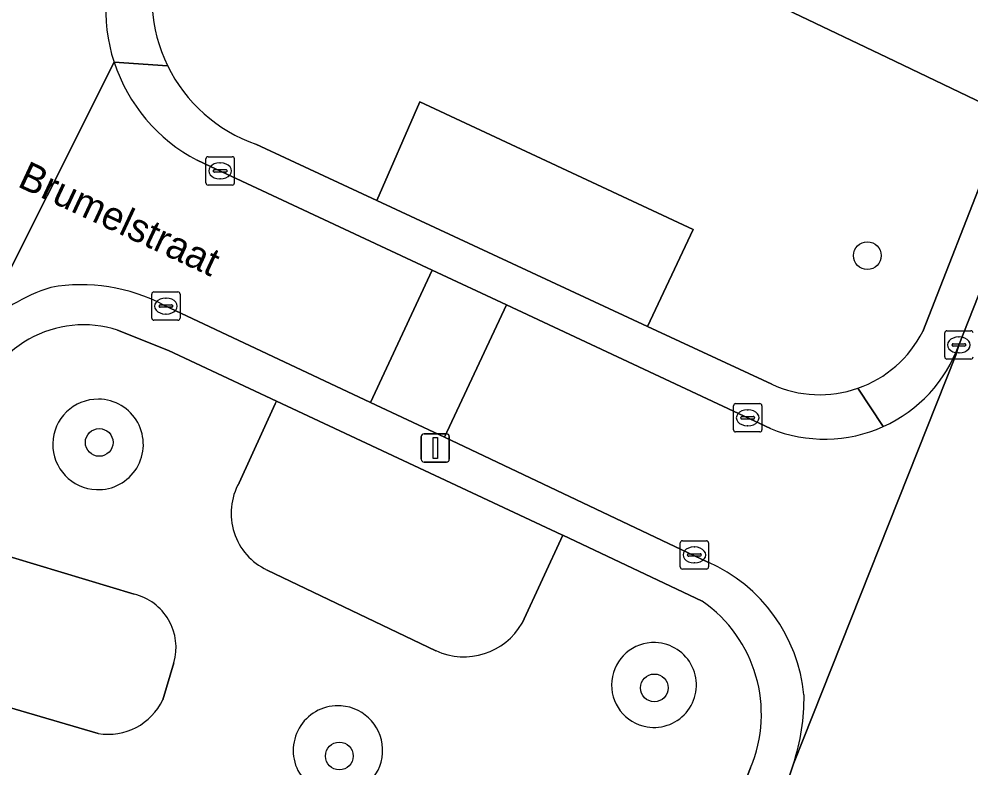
# Model space of a CAD drawing. Extents: x 159817 to 160765, y 380688 to 381638.
# Drawn here: x 160248.03 to 160281.64, y 381228.53 to 381254.99 of the extents above; entities that cross this region are included whole.
import ezdxf

# ---------------------------------------------------------------- set-up
doc = ezdxf.new("R2010")
doc.units = 0
for name, color, linetype in [('IMGEO_Boom', 7, 'Continuous'), ('IMGEO_Groenvoorziening', 7, 'Continuous'), ('IMGEO_Kolk', 7, 'Continuous'), ('IMGEO_Lichtmast', 7, 'Continuous'), ('IMGEO_Openbare_ruimte_label', 7, 'Continuous'), ('IMGEO_Rijbaan_lokaal_open', 7, 'Continuous'), ('IMGEO_Voetpad_open', 7, 'Continuous')]:
    doc.layers.add(name, color=color, linetype=linetype)

msp = doc.modelspace()

# ---------------------------------------------------------------- linework, layer by layer
at = {"layer": 'IMGEO_Boom'}
for centre in [(160277.982, 381246.629), (160250.861, 381240.029), (160270.46, 381231.359), (160259.338, 381228.952)]:
    msp.add_circle(centre, 0.489, dxfattribs=at)
at = {"layer": 'IMGEO_Groenvoorziening'}
for points in [[(160272.065, 381256.79), (160278.685, 381253.622), (160282.93, 381251.591), (160284.608, 381255.87), (160280.242, 381257.583), (160263.914, 381264.002), (160257.027, 381266.942), (160255.623, 381263.651), (160262.284, 381260.57), (160265.98, 381258.86)], [(160267.231, 381236.749), (160267.191, 381236.768), (160257.123, 381241.49), (160257.077, 381241.391), (160255.799, 381238.604)], [(160252.092, 381234.668), (160245.216, 381236.743), (160243.781, 381231.814), (160250.825, 381229.75)], [(160265.791, 381233.649), (160267.231, 381236.749)], [(160256.786, 381235.522), (160262.748, 381232.673)], [(160253.107, 381230.939), (160253.496, 381232.248)]]:
    msp.add_lwpolyline(points, dxfattribs=at)
msp.add_lwpolyline([(160262.176, 381252.064), (160260.664, 381248.573), (160270.213, 381244.128), (160271.829, 381247.547)], close=True, dxfattribs=at)
for centre, radius, start, end in [((160250.82, 381239.959), 1.599, 89.3897, 268.1383), ((160250.82, 381239.959), 1.599, 268.1402, 89.3877), ((160257.732, 381237.524), 2.214, 150.799, 244.716), ((160251.637, 381232.787), 1.936, 343.8475, 76.3941), ((160263.737, 381234.821), 2.364, 245.2691, 330.2968), ((160270.447, 381231.462), 1.498, 87.912, 260.5676), ((160270.447, 381231.462), 1.498, 260.5851, 87.8946), ((160251.179, 381231.856), 2.135, 260.4664, 334.5757), ((160259.29, 381229.15), 1.58, 86.1039, 266.9673), ((160259.288, 381229.15), 1.58, 267.0129, 86.0583)]:
    msp.add_arc(centre, radius, start, end, dxfattribs=at)
at = {"layer": 'IMGEO_Kolk'}
for p, q in [((160254.63, 381249.196), (160254.63, 381250.048)), ((160254.705, 381250.122), (160255.557, 381250.122)), ((160255.631, 381250.048), (160255.631, 381249.196)), ((160254.932, 381249.665), (160255.33, 381249.665)), ((160255.118, 381249.902), (160255.143, 381249.902)), ((160254.889, 381249.616), (160254.889, 381249.628)), ((160255.327, 381249.579), (160254.929, 381249.579)), ((160255.141, 381249.342), (160255.116, 381249.342)), ((160255.373, 381249.628), (160255.373, 381249.616)), ((160255.557, 381249.122), (160254.705, 381249.122)), ((160252.715, 381244.419), (160252.715, 381245.271)), ((160252.79, 381245.345), (160253.642, 381245.345)), ((160253.716, 381245.271), (160253.716, 381244.419)), ((160253.203, 381245.125), (160253.228, 381245.125)), ((160252.974, 381244.839), (160252.974, 381244.851)), ((160253.412, 381244.802), (160253.014, 381244.802)), ((160253.017, 381244.888), (160253.415, 381244.888)), ((160253.458, 381244.851), (160253.458, 381244.839)), ((160253.642, 381244.345), (160252.79, 381244.345)), ((160253.226, 381244.565), (160253.201, 381244.565)), ((160280.786, 381243.974), (160281.638, 381243.974)), ((160280.711, 381243.048), (160280.711, 381243.9)), ((160281.199, 381243.754), (160281.224, 381243.754)), ((160280.97, 381243.468), (160280.97, 381243.48)), ((160281.408, 381243.431), (160281.01, 381243.431)), ((160281.013, 381243.517), (160281.411, 381243.517)), ((160281.454, 381243.48), (160281.454, 381243.468)), ((160281.638, 381242.974), (160280.786, 381242.974)), ((160281.222, 381243.194), (160281.197, 381243.194)), ((160273.254, 381240.473), (160273.254, 381241.325)), ((160273.329, 381241.399), (160274.181, 381241.399)), ((160274.255, 381241.325), (160274.255, 381240.473)), ((160273.513, 381240.893), (160273.513, 381240.905)), ((160273.556, 381240.942), (160273.954, 381240.942)), ((160273.742, 381241.179), (160273.767, 381241.179)), ((160273.997, 381240.905), (160273.997, 381240.893)), ((160273.951, 381240.856), (160273.553, 381240.856)), ((160273.765, 381240.619), (160273.74, 381240.619)), ((160274.181, 381240.399), (160273.329, 381240.399)), ((160271.449, 381236.556), (160272.301, 381236.556)), ((160271.374, 381235.63), (160271.374, 381236.482)), ((160271.862, 381236.336), (160271.887, 381236.336)), ((160272.375, 381236.482), (160272.375, 381235.63)), ((160271.633, 381236.05), (160271.633, 381236.062)), ((160272.071, 381236.013), (160271.673, 381236.013)), ((160271.676, 381236.099), (160272.074, 381236.099)), ((160272.117, 381236.062), (160272.117, 381236.05)), ((160272.301, 381235.556), (160271.449, 381235.556)), ((160271.885, 381235.776), (160271.86, 381235.776))]:
    msp.add_line(p, q, dxfattribs=at)
for points in [[(160254.63, 381249.196), (160254.63, 381250.048)], [(160254.705, 381250.122), (160255.557, 381250.122)], [(160255.631, 381250.048), (160255.631, 381249.196)], [(160255.557, 381249.122), (160254.705, 381249.122)], [(160252.715, 381244.419), (160252.715, 381245.271)], [(160252.79, 381245.345), (160253.642, 381245.345)], [(160253.716, 381245.271), (160253.716, 381244.419)], [(160253.642, 381244.345), (160252.79, 381244.345)], [(160280.786, 381243.974), (160281.638, 381243.974)], [(160280.711, 381243.048), (160280.711, 381243.9)], [(160281.638, 381242.974), (160280.786, 381242.974)], [(160273.254, 381240.473), (160273.254, 381241.325)], [(160273.329, 381241.399), (160274.181, 381241.399)], [(160274.255, 381241.325), (160274.255, 381240.473)], [(160274.181, 381240.399), (160273.329, 381240.399)], [(160271.449, 381236.556), (160272.301, 381236.556)], [(160271.374, 381235.63), (160271.374, 381236.482)], [(160272.375, 381236.482), (160272.375, 381235.63)], [(160272.301, 381235.556), (160271.449, 381235.556)]]:
    msp.add_lwpolyline(points, dxfattribs=at)
for centre, radius, start, end in [((160254.707, 381250.046), 0.0765, 91.552, 178.448), ((160254.707, 381250.046), 0.0765, 91.552, 178.448), ((160255.555, 381250.046), 0.0765, 1.552, 88.448), ((160255.555, 381250.046), 0.0765, 1.552, 88.448), ((160254.929, 381249.625), 0.0403, 85.8775, 175.7526), ((160255.334, 381249.627), 0.0386, 1.7309, 96.639), ((160254.926, 381249.615), 0.0366, 178.938, 274.7102), ((160255.33, 381249.622), 0.043, 264.8664, 352.4533), ((160254.707, 381249.198), 0.0765, 181.552, 268.448), ((160254.707, 381249.198), 0.0765, 181.552, 268.448), ((160255.555, 381249.198), 0.0765, 271.552, 358.448), ((160255.555, 381249.198), 0.0765, 271.552, 358.448), ((160252.792, 381245.269), 0.0765, 91.552, 178.448), ((160252.792, 381245.269), 0.0765, 91.552, 178.448), ((160253.64, 381245.269), 0.0765, 1.552, 88.448), ((160253.64, 381245.269), 0.0765, 1.552, 88.448), ((160253.014, 381244.848), 0.0403, 85.8775, 175.7526), ((160253.011, 381244.838), 0.0366, 178.938, 274.7102), ((160253.415, 381244.845), 0.043, 264.8664, 352.4533), ((160253.419, 381244.85), 0.0386, 1.7309, 96.639), ((160252.792, 381244.421), 0.0765, 181.552, 268.448), ((160252.792, 381244.421), 0.0765, 181.552, 268.448), ((160253.64, 381244.421), 0.0765, 271.552, 358.448), ((160253.64, 381244.421), 0.0765, 271.552, 358.448), ((160280.788, 381243.898), 0.0765, 91.552, 178.448), ((160280.788, 381243.898), 0.0765, 91.552, 178.448), ((160281.636, 381243.898), 0.0765, 1.552, 88.448), ((160281.636, 381243.898), 0.0765, 1.552, 88.448), ((160281.01, 381243.477), 0.0403, 85.8775, 175.7526), ((160281.007, 381243.467), 0.0366, 178.938, 274.7102), ((160281.411, 381243.474), 0.043, 264.8664, 352.4533), ((160281.415, 381243.479), 0.0386, 1.7309, 96.639), ((160280.788, 381243.05), 0.0765, 181.552, 268.448), ((160280.788, 381243.05), 0.0765, 181.552, 268.448), ((160281.636, 381243.05), 0.0765, 271.552, 358.448), ((160281.636, 381243.05), 0.0765, 271.552, 358.448), ((160273.331, 381241.323), 0.0765, 91.552, 178.448), ((160273.331, 381241.323), 0.0765, 91.552, 178.448), ((160274.179, 381241.323), 0.0765, 1.552, 88.448), ((160274.179, 381241.323), 0.0765, 1.552, 88.448), ((160273.553, 381240.902), 0.0403, 85.8775, 175.7526), ((160273.958, 381240.904), 0.0386, 1.7309, 96.639), ((160273.55, 381240.892), 0.0366, 178.938, 274.7102), ((160273.954, 381240.899), 0.043, 264.8664, 352.4533), ((160273.331, 381240.475), 0.0765, 181.552, 268.448), ((160273.331, 381240.475), 0.0765, 181.552, 268.448), ((160274.179, 381240.475), 0.0765, 271.552, 358.448), ((160274.179, 381240.475), 0.0765, 271.552, 358.448), ((160271.451, 381236.48), 0.0765, 91.552, 178.448), ((160271.451, 381236.48), 0.0765, 91.552, 178.448), ((160272.299, 381236.48), 0.0765, 1.552, 88.448), ((160272.299, 381236.48), 0.0765, 1.552, 88.448), ((160271.673, 381236.059), 0.0403, 85.8775, 175.7526), ((160271.67, 381236.049), 0.0366, 178.938, 274.7102), ((160272.074, 381236.056), 0.043, 264.8664, 352.4533), ((160272.078, 381236.061), 0.0386, 1.7309, 96.639), ((160271.451, 381235.632), 0.0765, 181.552, 268.448), ((160271.451, 381235.632), 0.0765, 181.552, 268.448), ((160272.299, 381235.632), 0.0765, 271.552, 358.448), ((160272.299, 381235.632), 0.0765, 271.552, 358.448)]:
    msp.add_arc(centre, radius, start, end, dxfattribs=at)
for centre, major_axis, ratio, start_param, end_param in [((160255.117, 381249.622), (-0.387, 0.002), 0.722429, 4.712389, 7.853982), ((160255.142, 381249.622), (-0.39, 0.002), 0.717154, 1.570796, 4.712389), ((160253.202, 381244.845), (-0.387, 0.002), 0.722429, 4.712389, 7.853982), ((160253.227, 381244.845), (-0.39, 0.002), 0.717154, 1.570796, 4.712389), ((160281.198, 381243.474), (-0.387, 0.002), 0.722429, 4.712389, 7.853982), ((160281.223, 381243.474), (-0.39, 0.002), 0.717154, 1.570796, 4.712389), ((160273.741, 381240.899), (-0.387, 0.002), 0.722429, 4.712389, 7.853982), ((160273.766, 381240.899), (-0.39, 0.002), 0.717154, 1.570796, 4.712389), ((160271.861, 381236.056), (-0.387, 0.002), 0.722429, 4.712389, 7.853982), ((160271.886, 381236.056), (-0.39, 0.002), 0.717154, 1.570796, 4.712389)]:
    msp.add_ellipse(centre, major_axis=major_axis, ratio=ratio, start_param=start_param, end_param=end_param, dxfattribs=at)
at = {"layer": 'IMGEO_Lichtmast'}
for p, q in [((160262.229, 381239.434), (160262.229, 381240.234)), ((160262.229, 381240.234), (160262.229, 381239.434)), ((160262.329, 381240.334), (160263.119, 381240.334)), ((160263.119, 381240.334), (160262.329, 381240.334)), ((160263.219, 381240.234), (160263.219, 381239.434)), ((160263.219, 381239.434), (160263.219, 381240.234)), ((160263.119, 381239.334), (160262.329, 381239.334)), ((160262.329, 381239.334), (160263.119, 381239.334))]:
    msp.add_line(p, q, dxfattribs=at)
msp.add_lwpolyline([(160262.649, 381240.209), (160262.799, 381240.209), (160262.799, 381239.459), (160262.649, 381239.459), (160262.649, 381240.209)], dxfattribs=at)
for centre, start, end in [((160262.329, 381240.234), 90, 180), ((160262.329, 381240.234), 90, 180), ((160263.119, 381240.234), 0, 90), ((160263.119, 381240.234), 360, 90), ((160262.329, 381239.434), 180, 270), ((160262.329, 381239.434), 180, 270), ((160263.119, 381239.434), 270, 0), ((160263.119, 381239.434), 270, 0)]:
    msp.add_arc(centre, 0.1, start, end, dxfattribs=at)
at = {"layer": 'IMGEO_Rijbaan_lokaal_open'}
for points in [[(160281.271, 381226.443), (160299.09, 381271.369), (160307.058, 381291.325), (160316.946, 381316.648), (160311.054, 381318.986), (160304.324, 381302.023), (160283.79, 381250), (160281.212, 381243.47), (160281.107, 381243.114), (160275.368, 381228.672), (160275.08, 381227.786), (160271.695, 381219.129), (160267.546, 381205.381), (160267.463, 381204.669), (160266.535, 381197.216)], [(160246.635, 381243.993), (160251.385, 381253.463)], [(160251.385, 381253.463), (160246.635, 381243.993)], [(160254.784, 381249.779), (160254.316, 381250)], [(160253.145, 381244.876), (160260.434, 381241.444), (160262.619, 381246.111), (160254.784, 381249.779)], [(160274.56, 381240.521), (160265.236, 381244.886), (160263.049, 381240.213), (160272.354, 381235.804)], [(160275.368, 381228.672), (160281.107, 381243.114), (160281.212, 381243.47)]]:
    msp.add_lwpolyline(points, dxfattribs=at)
msp.add_lwpolyline([(160262.619, 381246.111), (160260.434, 381241.444), (160263.049, 381240.213), (160265.236, 381244.886)], close=True, dxfattribs=at)
for centre, radius, start, end in [((160257.11, 381255.334), 6.023, 153.8413, 198.0954), ((160257.11, 381255.336), 6.023, 198.1206, 242.3669), ((160251.054, 381239.487), 6.311, 107.5558, 134.4387), ((160250.24, 381239.42), 6.181, 61.9724, 100.1604), ((160276.467, 381245.193), 5.048, 294.2948, 340.0422), ((160276.469, 381245.197), 5.051, 247.7881, 294.2539), ((160270.021, 381230.549), 5.75, 5.621, 66.0596), ((160268.151, 381231.03), 7.593, 341.9069, 0.6185)]:
    msp.add_arc(centre, radius, start, end, dxfattribs=at)
at = {"layer": 'IMGEO_Voetpad_open'}
for points in [[(160281.212, 381243.47), (160283.79, 381250), (160304.324, 381302.023), (160311.054, 381318.986), (160324.621, 381353.178), (160325.632, 381355.733), (160325.775, 381356.504), (160325.752, 381356.962), (160325.818, 381357.454), (160331.894, 381372.811)], [(160327.681, 381364.751), (160306.429, 381310.967), (160304.091, 381305.049), (160298.844, 381291.771), (160298.304, 381290.405), (160295.93, 381284.397), (160295.376, 381282.993), (160293.027, 381277.05), (160292.429, 381275.535), (160290.157, 381269.786), (160289.589, 381268.347), (160287.291, 381262.532), (160285.593, 381258.382), (160284.608, 381255.87), (160282.93, 381251.591), (160282.306, 381250), (160279.935, 381243.953)], [(160278.685, 381253.622), (160272.065, 381256.79)], [(160253.274, 381253.338), (160251.385, 381253.463)], [(160251.385, 381253.463), (160253.274, 381253.338)], [(160279.935, 381243.953), (160282.306, 381250), (160282.93, 381251.591), (160278.685, 381253.622)], [(160256.394, 381250.56), (160257.597, 381250), (160260.664, 381248.573), (160262.176, 381252.064), (160271.829, 381247.547), (160270.213, 381244.128), (160274.609, 381242.082)], [(160260.664, 381248.573), (160257.597, 381250), (160256.394, 381250.56)], [(160254.316, 381250), (160254.784, 381249.779), (160262.619, 381246.111), (160265.236, 381244.886), (160274.56, 381240.521)], [(160274.609, 381242.082), (160270.213, 381244.128), (160260.664, 381248.573)], [(160272.354, 381235.804), (160263.049, 381240.213), (160260.434, 381241.444), (160253.145, 381244.876)], [(160255.799, 381238.604), (160257.077, 381241.391), (160257.123, 381241.49), (160253.312, 381243.278), (160251.511, 381243.995)], [(160251.511, 381243.995), (160253.312, 381243.278), (160257.123, 381241.49), (160267.191, 381236.768), (160267.231, 381236.749), (160272.154, 381234.422)], [(160278.544, 381240.592), (160277.649, 381241.945)], [(160277.649, 381241.945), (160278.544, 381240.592)], [(160246.498, 381241.147), (160245.216, 381236.743), (160252.092, 381234.668)], [(160272.154, 381234.422), (160267.231, 381236.749), (160265.791, 381233.649)], [(160262.748, 381232.673), (160256.786, 381235.522)], [(160253.496, 381232.248), (160253.107, 381230.939)], [(160250.825, 381229.75), (160243.781, 381231.814), (160241.315, 381223.346), (160247.305, 381221.447), (160249.613, 381220.715), (160250.189, 381220.532), (160251.179, 381223.65)], [(160273.86, 381228.53), (160272.472, 381225.02), (160271.906, 381223.588), (160271.359, 381222.034), (160268.762, 381214.643), (160266.993, 381208.842), (160264.718, 381201.384), (160255.658, 381167.83), (160255.528, 381167.35), (160254.334, 381162.942), (160253.975, 381161.663), (160251.97, 381154.51), (160251.548, 381153.059), (160249.944, 381147.243), (160249.487, 381145.85), (160247.915, 381140.108), (160247.058, 381136.994), (160246.977, 381136.698), (160246.121, 381133.645), (160246.041, 381133.358), (160245.124, 381130.087), (160244.977, 381129.563)], [(160266.052, 381227.505), (160272.472, 381225.02), (160273.86, 381228.53)], [(160266.535, 381197.216), (160267.463, 381204.669), (160267.546, 381205.381), (160271.695, 381219.129), (160275.08, 381227.786), (160275.368, 381228.672)]]:
    msp.add_lwpolyline(points, dxfattribs=at)
for centre, radius, start, end in [((160257.11, 381255.334), 6.023, 153.8413, 198.0954), ((160258.228, 381255.757), 5.513, 161.5009, 206.0214), ((160258.228, 381255.757), 5.513, 161.5009, 206.0214), ((160257.11, 381255.336), 6.023, 198.1206, 242.3669), ((160258.223, 381255.755), 5.507, 206.0292, 250.608), ((160258.223, 381255.755), 5.507, 206.0292, 250.608), ((160251.054, 381239.487), 6.311, 107.5558, 134.4387), ((160250.24, 381239.42), 6.181, 61.9724, 100.1604), ((160250.309, 381240.274), 3.91, 72.0998, 167.104), ((160250.309, 381240.274), 3.91, 72.0998, 167.104), ((160276.305, 381245.78), 4.064, 289.313, 333.2786), ((160276.305, 381245.78), 4.064, 289.313, 333.2786), ((160276.467, 381245.193), 5.048, 294.2948, 340.0422), ((160276.299, 381245.789), 4.074, 245.4902, 289.3492), ((160276.299, 381245.789), 4.074, 245.4902, 289.3492), ((160250.82, 381239.959), 1.599, 89.3897, 268.1383), ((160250.82, 381239.959), 1.599, 268.1402, 89.3877), ((160276.469, 381245.197), 5.051, 247.7881, 294.2539), ((160257.732, 381237.524), 2.214, 150.799, 244.716), ((160270.021, 381230.549), 5.75, 5.621, 66.0596), ((160251.637, 381232.787), 1.936, 343.8475, 76.3941), ((160269.351, 381230.418), 4.888, 337.2825, 55.0137), ((160269.351, 381230.418), 4.888, 337.2825, 55.0137), ((160263.737, 381234.821), 2.364, 245.2691, 330.2968), ((160270.447, 381231.462), 1.498, 87.912, 260.5676), ((160270.447, 381231.462), 1.498, 260.5851, 87.8946), ((160251.179, 381231.856), 2.135, 260.4664, 334.5757), ((160268.151, 381231.03), 7.593, 341.9069, 0.6185), ((160259.29, 381229.15), 1.58, 86.1039, 266.9673), ((160259.288, 381229.15), 1.58, 267.0129, 86.0583)]:
    msp.add_arc(centre, radius, start, end, dxfattribs=at)

# ---------------------------------------------------------------- texts
at = {"layer": 'IMGEO_Openbare_ruimte_label'}
msp.add_text('Brumelstraat', height=1, rotation=334.9727, dxfattribs=at).set_placement((160247.937, 381249.086))

doc.saveas('drawing.dxf')
